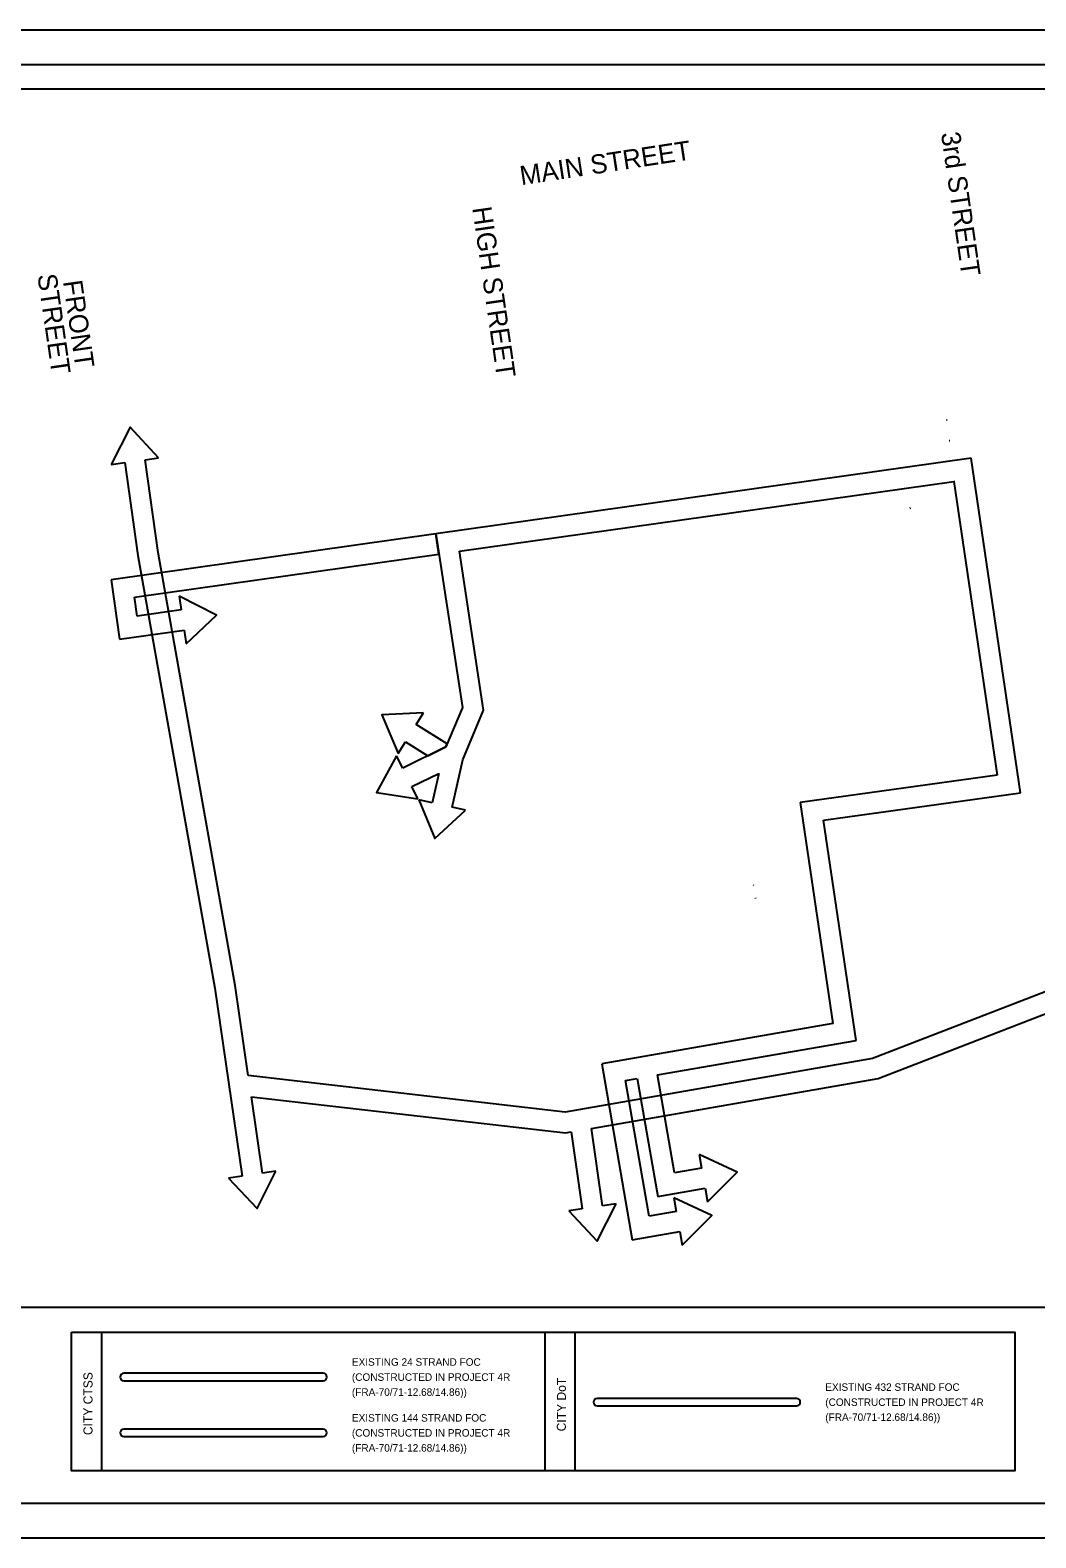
# Model space of a CAD drawing. Extents: x 1826739 to 1830139, y 710816 to 713016.
# Drawn here: x 1827883 to 1829350, y 710816 to 713016 of the extents above; entities that cross this region are included whole.
import ezdxf

# ---------------------------------------------------------------- set-up
doc = ezdxf.new("R2010")
doc.units = 0
for name, color, linetype in [('POOLS', 7, 'Continuous'), ('SH_Border', 7, 'Continuous'), ('SH_Cut_Line', 7, 'Continuous'), ('SH_Data', 7, 'Continuous'), ('TX_P_100', 7, 'Continuous')]:
    doc.layers.add(name, color=color, linetype=linetype)

msp = doc.modelspace()

# ---------------------------------------------------------------- linework, layer by layer
at = {"layer": 'POOLS'}
msp.add_lwpolyline([(1826938.7, 711152.7), (1829988.7, 711152.7), (1829988.7, 712929.8), (1826938.7, 712929.8)], close=True, dxfattribs=at)
at = {"layer": 'SH_Border'}
for p, q in [((1827986.8, 711115.8), (1827986.8, 710913.5)), ((1828634, 711115.8), (1828634, 710913.5)), ((1828677.7, 711115.8), (1828677.7, 710913.5))]:
    msp.add_line(p, q, dxfattribs=at)
for points in [[(1826938.7, 712965.9), (1830088.7, 712965.9), (1830088.7, 710865.9), (1826938.7, 710865.9)], [(1827943.1, 711115.8), (1829319.7, 711115.8), (1829319.7, 710913.5), (1827943.1, 710913.5)]]:
    msp.add_lwpolyline(points, close=True, dxfattribs=at)
at = {"layer": 'SH_Cut_Line'}
msp.add_lwpolyline([(1826738.7, 710815.9), (1830138.7, 710815.9), (1830138.7, 713015.9), (1826738.7, 713015.9)], close=True, dxfattribs=at)
at = {"layer": 'SH_Data'}
for p, q in [((1829220.8, 712447), (1829219.9, 712446.8)), ((1829224.1, 712417.1), (1829225, 712417.3)), ((1828000.8, 712382.1), (1828020.6, 712384.9)), ((1828020.6, 712384.9), (1828039.8, 712249.3)), ((1828050.3, 712389.1), (1828070.1, 712391.9)), ((1828069.5, 712253.6), (1828050.3, 712389.1)), ((1829255.9, 712391.3), (1828474.8, 712280.9)), ((1829327.9, 711903.2), (1829255.9, 712391.3)), ((1828509.1, 712255.4), (1829230.6, 712357.5)), ((1829230.4, 712358.4), (1829230.5, 712357.5)), ((1829230.6, 712357.5), (1829293.8, 711928.7)), ((1829167.7, 712318.2), (1829166.7, 712318.1)), ((1829264.8, 712331.1), (1829264.6, 712332.1)), ((1828474.8, 712280.9), (1828000.9, 712213.9)), ((1828474.8, 712280.9), (1828513.4, 712027.4)), ((1828479.3, 712251.2), (1828474.8, 712280.9)), ((1828034.8, 712188.4), (1828479.3, 712251.2)), ((1828069.5, 712253.6), (1828069.5, 712253.6)), ((1828069.5, 712253.6), (1828069.5, 712253.6)), ((1828181.9, 711622.1), (1828069.5, 712253.6)), ((1828544.3, 712023.6), (1828509.1, 712255.4)), ((1828039.8, 712249.3), (1828039.8, 712249.3)), ((1828039.8, 712249.3), (1828039.8, 712249.3)), ((1828039.8, 712249.3), (1828152.2, 711617.9)), ((1828000.9, 712213.9), (1828013.2, 712127)), ((1828038.7, 712160.9), (1828034.8, 712188.4)), ((1828100.3, 712189.9), (1828103.1, 712170.1)), ((1828103.1, 712170.1), (1828038.7, 712160.9)), ((1828103.1, 712170.1), (1828103.1, 712170.1)), ((1828103.1, 712170.1), (1828103.1, 712170.1)), ((1828013.2, 712127), (1828107.3, 712140.4)), ((1828107.3, 712140.4), (1828107.3, 712140.4)), ((1828107.3, 712140.4), (1828110.1, 712120.6)), ((1828101.4, 712027.5), (1828101.4, 712027.5)), ((1828446.2, 712002.8), (1828456.8, 712019.8)), ((1828491.3, 711974.6), (1828446.2, 712002.8)), ((1828446.2, 712002.8), (1828446.2, 712002.8)), ((1828419.6, 711960.4), (1828430.3, 711977.4)), ((1828489.4, 711970), (1828426.4, 711939)), ((1828430.3, 711977.4), (1828430.3, 711977.4)), ((1828430.3, 711977.4), (1828430.3, 711977.4)), ((1828430.3, 711977.4), (1828462.9, 711957)), ((1828426.4, 711939), (1828417.5, 711956.9)), ((1828462.9, 711957), (1828462.9, 711957)), ((1828498.7, 711881.9), (1828514, 711951.2)), ((1828426.4, 711939), (1828426.4, 711939)), ((1828439.6, 711912.1), (1828478.9, 711931.4)), ((1828478.9, 711931.4), (1828469.4, 711888.4)), ((1829293.8, 711928.7), (1829006.5, 711888.7)), ((1828448.5, 711894.1), (1828439.6, 711912.1)), ((1828439.6, 711912.1), (1828439.6, 711912.1)), ((1828439.6, 711912.1), (1828439.6, 711912.1)), ((1829040.6, 711863.2), (1829327.9, 711903.2)), ((1828469.4, 711888.4), (1828449.9, 711892.7)), ((1828469.4, 711888.4), (1828469.4, 711888.4)), ((1828518.2, 711877.6), (1828498.7, 711881.9)), ((1828498.7, 711881.9), (1828498.7, 711881.9)), ((1828498.7, 711881.9), (1828498.7, 711881.9)), ((1829006.5, 711888.7), (1829054, 711566.3)), ((1829088, 711541.8), (1829040.6, 711863.2)), ((1828938.6, 711767.6), (1828938.4, 711768.5)), ((1828941, 711749.8), (1828941.2, 711748.8)), ((1828152.2, 711617.9), (1828152.2, 711617.9)), ((1828152.2, 711617.9), (1828152.2, 711617.9)), ((1828152.2, 711617.9), (1828152.2, 711617.9)), ((1828152.2, 711617.9), (1828191.9, 711343.7)), ((1828201, 711490.4), (1828181.9, 711622.1)), ((1828181.9, 711622.1), (1828181.9, 711622.1)), ((1828181.9, 711622.1), (1828181.9, 711622.1)), ((1828181.9, 711622.1), (1828181.9, 711622.1)), ((1828181.9, 711622.1), (1828181.9, 711622.1)), ((1829414.6, 711632.1), (1829112.1, 711515.2)), ((1829120.2, 711486.1), (1829421, 711602.4)), ((1829054, 711566.3), (1828716.9, 711507.6)), ((1828798.2, 711491.3), (1829088, 711541.8)), ((1829112.1, 711515.2), (1828663.3, 711437.1)), ((1828716.9, 711507.6), (1828761.5, 711250.7)), ((1828663.3, 711437.1), (1828201, 711490.4)), ((1828701.8, 711413.4), (1829120.2, 711486.1)), ((1828751.6, 711483.2), (1828768.6, 711486.1)), ((1828785.9, 711285.4), (1828751.6, 711483.2)), ((1828768.6, 711486.1), (1828798.6, 711313.9)), ((1828823, 711348.6), (1828798.2, 711491.3)), ((1828221.6, 711348), (1828205.5, 711459.6)), ((1828205.5, 711459.6), (1828664, 711406.8)), ((1828664, 711406.8), (1828672, 711408.2)), ((1828672, 711408.2), (1828688.4, 711296)), ((1828718.1, 711300.3), (1828701.8, 711413.4)), ((1828859, 711375.2), (1828862.5, 711355.5)), ((1828241.4, 711350.8), (1828221.6, 711348)), ((1828862.5, 711355.5), (1828823, 711348.6)), ((1828862.5, 711355.5), (1828862.5, 711355.5)), ((1828862.5, 711355.5), (1828862.5, 711355.5)), ((1828191.9, 711343.7), (1828172.1, 711340.8)), ((1828798.6, 711313.9), (1828867.6, 711325.9)), ((1828822, 711312), (1828825.4, 711292.3)), ((1828867.6, 711325.9), (1828867.6, 711325.9)), ((1828867.6, 711325.9), (1828871, 711306.2)), ((1828688.4, 711296), (1828668.6, 711293.2)), ((1828737.9, 711303.2), (1828718.1, 711300.3)), ((1828825.4, 711292.3), (1828785.9, 711285.4)), ((1828825.4, 711292.3), (1828825.4, 711292.3)), ((1828825.4, 711292.3), (1828825.4, 711292.3)), ((1828761.5, 711250.7), (1828830.6, 711262.8)), ((1828830.6, 711262.8), (1828830.6, 711262.8)), ((1828830.6, 711262.8), (1828834, 711243)), ((1828310.2, 711056), (1828019.2, 711056)), ((1828019.2, 711045.1), (1828310.2, 711045.1)), ((1828310.5, 711056), (1828310.2, 711056)), ((1829001.1, 711019.4), (1828710.2, 711019.4)), ((1829001.4, 711019.4), (1829001.1, 711019.4)), ((1828710.2, 711008.5), (1829001.1, 711008.5)), ((1828310.2, 710974.6), (1828019.2, 710974.6)), ((1828310.5, 710974.6), (1828310.2, 710974.6)), ((1828019.2, 710963.7), (1828310.2, 710963.7))]:
    msp.add_line(p, q, dxfattribs=at)
for points in [[(1828070.1, 712391.9), (1828028.5, 712436.5), (1828000.8, 712382.1)], [(1828110.1, 712120.6), (1828154.7, 712162.2), (1828100.3, 712189.9)], [(1828456.8, 712019.8), (1828395.8, 712016.6), (1828419.6, 711960.4)], [(1828513.4, 712027.4), (1828489.4, 711970)], [(1828514, 711951.2), (1828544.3, 712023.6)], [(1828462.9, 711957), (1828489.4, 711970), (1828491.3, 711974.6)], [(1828417.5, 711956.9), (1828388.1, 711903.4), (1828448.5, 711894.1)], [(1828449.9, 711892.7), (1828473.2, 711836.3), (1828518.2, 711877.6)], [(1828871, 711306.2), (1828914.3, 711349.3), (1828859, 711375.2)], [(1828172.1, 711340.8), (1828213.9, 711296.4), (1828241.4, 711350.8)], [(1828834, 711243), (1828877.3, 711286.1), (1828822, 711312)], [(1828668.6, 711293.2), (1828710.4, 711248.7), (1828737.9, 711303.2)]]:
    msp.add_lwpolyline(points, dxfattribs=at)
for centre, radius, start, end in [((1828415.7, 712046.2), 15, 190.4582, 190.4582), ((1828019.4, 711050.5), 5.46, 91.7926, 268.2074), ((1828310.3, 711050.5), 5.46, 271.7926, 88.2074), ((1828710.3, 711013.9), 5.46, 91.7926, 268.2074), ((1829001.2, 711013.9), 5.46, 271.7926, 88.2074), ((1828019.4, 710969.1), 5.46, 91.7926, 268.2074), ((1828310.3, 710969.1), 5.46, 271.7926, 88.2074)]:
    msp.add_arc(centre, radius, start, end, dxfattribs=at)

# ---------------------------------------------------------------- texts
for s, p in [('EXISTING 24 STRAND FOC', (1828352.2, 711067)), ('(CONSTRUCTED IN PROJECT 4R', (1828352.2, 711045)), ('EXISTING 432 STRAND FOC', (1829043.1, 711030.4)), ('(FRA-70/71-12.68/14.86))', (1828352.2, 711023.1)), ('(CONSTRUCTED IN PROJECT 4R', (1829043.1, 711008.4)), ('EXISTING 144 STRAND FOC', (1828352.2, 710985.5)), ('(FRA-70/71-12.68/14.86))', (1829043.1, 710986.5)), ('(CONSTRUCTED IN PROJECT 4R', (1828352.2, 710963.6)), ('(FRA-70/71-12.68/14.86))', (1828352.2, 710941.7))]:
    msp.add_text(s, height=10.957, dxfattribs=at).set_placement(p)
for s, p in [('CITY CTSS', (1827973.6, 710965.8)), ('CITY DoT', (1828664.5, 710971.3))]:
    msp.add_text(s, height=13.15, rotation=90, dxfattribs=at).set_placement(p)
at = {"layer": 'TX_P_100'}
for s, rotation, p in [('3rd STREET', 278.2126, (1829211.9, 712865.5)), ('MAIN STREET', 8.6541, (1828599.5, 712789.5)), ('HIGH STREET', 278.2126, (1828527.8, 712756.5)), ('STREET', 278.2126, (1827893.1, 712658.5)), ('FRONT', 278.2126, (1827930.5, 712649.2))]:
    msp.add_text(s, height=28, rotation=rotation, dxfattribs=at).set_placement(p)

doc.saveas('drawing.dxf')
